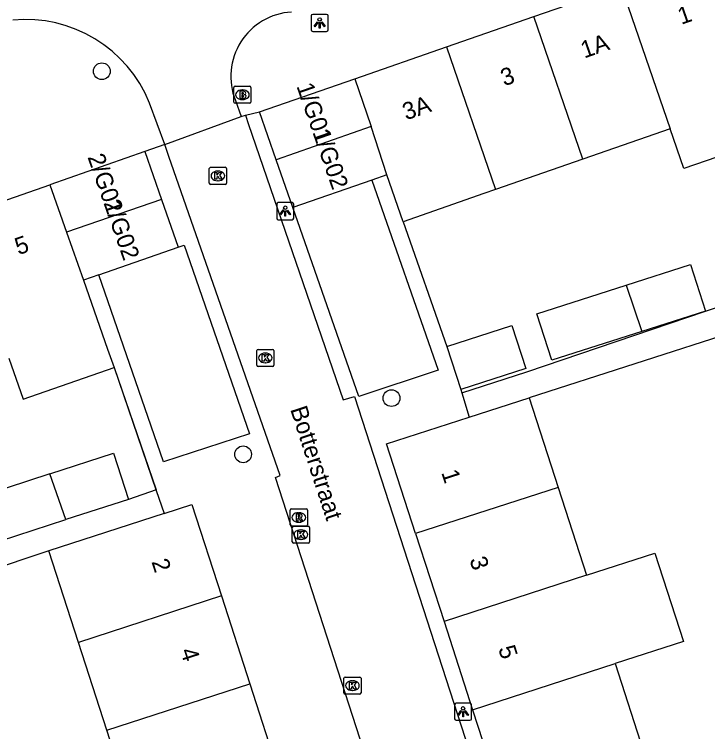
# Model space of a CAD drawing. Extents: x 159377 to 159983, y 382996 to 383595.
# Drawn here: x 159638.52 to 159679.02, y 383252.43 to 383294.33 of the extents above; entities that cross this region are included whole.
import ezdxf

# ---------------------------------------------------------------- set-up
doc = ezdxf.new("R2010")
doc.units = 0
for name, color, linetype in [('IMGEO_Boom', 7, 'Continuous'), ('IMGEO_Brandkraan', 7, 'Continuous'), ('IMGEO_Kolk', 7, 'Continuous'), ('IMGEO_Lichtpunt', 7, 'Continuous'), ('IMGEO_Muur', 7, 'Continuous'), ('IMGEO_Openbare_ruimte_label', 7, 'Continuous'), ('IMGEO_Pand', 7, 'Continuous'), ('IMGEO_Pand_nummerreeks', 7, 'Continuous'), ('IMGEO_Rijbaan_lokaal_open', 7, 'Continuous'), ('IMGEO_Rioolput', 7, 'Continuous'), ('IMGEO_Voetpad_open', 7, 'Continuous')]:
    doc.layers.add(name, color=color, linetype=linetype)

msp = doc.modelspace()

# ---------------------------------------------------------------- linework, layer by layer
at = {"layer": 'IMGEO_Boom'}
for centre in [(159643.634, 383291.001), (159660.553, 383271.913), (159651.886, 383268.63)]:
    msp.add_circle(centre, 0.489, dxfattribs=at)
at = {"layer": 'IMGEO_Brandkraan'}
for p, q in [((159651.418, 383290.129), (159652.27, 383290.129)), ((159651.343, 383289.203), (159651.343, 383290.055)), ((159651.831, 383289.909), (159651.856, 383289.909)), ((159652.344, 383290.055), (159652.344, 383289.203)), ((159651.854, 383289.349), (159651.829, 383289.349)), ((159652.27, 383289.129), (159651.418, 383289.129))]:
    msp.add_line(p, q, dxfattribs=at)
for points in [[(159651.418, 383290.129), (159652.27, 383290.129)], [(159651.343, 383289.203), (159651.343, 383290.055)], [(159651.691, 383289.829), (159651.691, 383289.429), (159651.904, 383289.429)], [(159651.922, 383289.829), (159651.691, 383289.829)], [(159651.87, 383289.748), (159651.816, 383289.748), (159651.816, 383289.672)], [(159651.816, 383289.672), (159651.869, 383289.672)], [(159652.344, 383290.055), (159652.344, 383289.203)], [(159651.878, 383289.596), (159651.816, 383289.596), (159651.816, 383289.515)], [(159651.816, 383289.515), (159651.878, 383289.515)], [(159652.27, 383289.129), (159651.418, 383289.129)]]:
    msp.add_lwpolyline(points, dxfattribs=at)
for centre, radius, start, end in [((159651.42, 383290.053), 0.0765, 91.552, 178.448), ((159651.42, 383290.053), 0.0765, 91.552, 178.448), ((159652.268, 383290.053), 0.0765, 1.552, 88.448), ((159652.268, 383290.053), 0.0765, 1.552, 88.448), ((159651.871, 383289.71), 0.0379, 267.8285, 90.9355), ((159651.926, 383289.684), 0.145, 59.4692, 91.5367), ((159651.951, 383289.731), 0.0922, 285.5137, 58.1501), ((159651.956, 383289.539), 0.105, 301.3115, 78.989), ((159651.879, 383289.555), 0.0404, 269.8759, 90.5077), ((159651.91, 383289.68), 0.251, 268.6676, 293.5347), ((159651.42, 383289.205), 0.0765, 181.552, 268.448), ((159651.42, 383289.205), 0.0765, 181.552, 268.448), ((159652.268, 383289.205), 0.0765, 271.552, 358.448), ((159652.268, 383289.205), 0.0765, 271.552, 358.448)]:
    msp.add_arc(centre, radius, start, end, dxfattribs=at)
for centre, major_axis, ratio, start_param, end_param in [((159651.83, 383289.629), (-0.387, 0.002), 0.722429, 4.712389, 7.853982), ((159651.855, 383289.629), (-0.39, 0.002), 0.717154, 1.570796, 4.712389)]:
    msp.add_ellipse(centre, major_axis=major_axis, ratio=ratio, start_param=start_param, end_param=end_param, dxfattribs=at)
at = {"layer": 'IMGEO_Kolk'}
for p, q in [((159649.912, 383284.465), (159649.912, 383285.317)), ((159649.987, 383285.391), (159650.839, 383285.391)), ((159650.4, 383285.171), (159650.425, 383285.171)), ((159650.913, 383285.317), (159650.913, 383284.465)), ((159650.839, 383284.391), (159649.987, 383284.391)), ((159650.423, 383284.611), (159650.398, 383284.611)), ((159652.684, 383273.835), (159652.684, 383274.687)), ((159652.759, 383274.761), (159653.611, 383274.761)), ((159653.685, 383274.687), (159653.685, 383273.835)), ((159653.172, 383274.541), (159653.197, 383274.541)), ((159653.611, 383273.761), (159652.759, 383273.761)), ((159653.195, 383273.981), (159653.17, 383273.981)), ((159654.759, 383263.514), (159654.759, 383264.366)), ((159654.834, 383264.44), (159655.686, 383264.44)), ((159655.247, 383264.22), (159655.272, 383264.22)), ((159655.76, 383264.366), (159655.76, 383263.514)), ((159655.686, 383263.44), (159654.834, 383263.44)), ((159655.27, 383263.66), (159655.245, 383263.66)), ((159657.772, 383254.698), (159657.772, 383255.55)), ((159657.847, 383255.624), (159658.699, 383255.624)), ((159658.26, 383255.404), (159658.285, 383255.404)), ((159658.773, 383255.55), (159658.773, 383254.698)), ((159658.699, 383254.624), (159657.847, 383254.624)), ((159658.283, 383254.844), (159658.258, 383254.844))]:
    msp.add_line(p, q, dxfattribs=at)
for points in [[(159649.912, 383284.465), (159649.912, 383285.317)], [(159649.987, 383285.391), (159650.839, 383285.391)], [(159650.233, 383285.091), (159650.356, 383285.091), (159650.356, 383284.94), (159650.486, 383285.091), (159650.65, 383285.091), (159650.504, 383284.94), (159650.657, 383284.691), (159650.505, 383284.691), (159650.42, 383284.855), (159650.356, 383284.788), (159650.356, 383284.691), (159650.233, 383284.691), (159650.233, 383285.091)], [(159650.913, 383285.317), (159650.913, 383284.465)], [(159650.839, 383284.391), (159649.987, 383284.391)], [(159652.684, 383273.835), (159652.684, 383274.687)], [(159652.759, 383274.761), (159653.611, 383274.761)], [(159653.685, 383274.687), (159653.685, 383273.835)], [(159653.005, 383274.461), (159653.128, 383274.461), (159653.128, 383274.31), (159653.258, 383274.461), (159653.422, 383274.461), (159653.276, 383274.31), (159653.429, 383274.061), (159653.277, 383274.061), (159653.192, 383274.225), (159653.128, 383274.158), (159653.128, 383274.061), (159653.005, 383274.061), (159653.005, 383274.461)], [(159653.611, 383273.761), (159652.759, 383273.761)], [(159654.759, 383263.514), (159654.759, 383264.366)], [(159654.834, 383264.44), (159655.686, 383264.44)], [(159655.08, 383264.14), (159655.203, 383264.14), (159655.203, 383263.989), (159655.333, 383264.14), (159655.497, 383264.14), (159655.351, 383263.989), (159655.504, 383263.74), (159655.352, 383263.74), (159655.267, 383263.904), (159655.203, 383263.837), (159655.203, 383263.74), (159655.08, 383263.74), (159655.08, 383264.14)], [(159655.76, 383264.366), (159655.76, 383263.514)], [(159655.686, 383263.44), (159654.834, 383263.44)], [(159657.772, 383254.698), (159657.772, 383255.55)], [(159657.847, 383255.624), (159658.699, 383255.624)], [(159658.093, 383255.324), (159658.216, 383255.324), (159658.216, 383255.173), (159658.346, 383255.324), (159658.51, 383255.324), (159658.364, 383255.173), (159658.517, 383254.924), (159658.365, 383254.924), (159658.28, 383255.088), (159658.216, 383255.021), (159658.216, 383254.924), (159658.093, 383254.924), (159658.093, 383255.324)], [(159658.773, 383255.55), (159658.773, 383254.698)], [(159658.699, 383254.624), (159657.847, 383254.624)]]:
    msp.add_lwpolyline(points, dxfattribs=at)
for centre, start, end in [((159649.989, 383285.315), 91.552, 178.448), ((159649.989, 383285.315), 91.552, 178.448), ((159650.837, 383285.315), 1.552, 88.448), ((159650.837, 383285.315), 1.552, 88.448), ((159649.989, 383284.467), 181.552, 268.448), ((159649.989, 383284.467), 181.552, 268.448), ((159650.837, 383284.467), 271.552, 358.448), ((159650.837, 383284.467), 271.552, 358.448), ((159652.761, 383274.685), 91.552, 178.448), ((159652.761, 383274.685), 91.552, 178.448), ((159653.609, 383274.685), 1.552, 88.448), ((159653.609, 383274.685), 1.552, 88.448), ((159652.761, 383273.837), 181.552, 268.448), ((159652.761, 383273.837), 181.552, 268.448), ((159653.609, 383273.837), 271.552, 358.448), ((159653.609, 383273.837), 271.552, 358.448), ((159654.836, 383264.364), 91.552, 178.448), ((159654.836, 383264.364), 91.552, 178.448), ((159655.684, 383264.364), 1.552, 88.448), ((159655.684, 383264.364), 1.552, 88.448), ((159654.836, 383263.516), 181.552, 268.448), ((159654.836, 383263.516), 181.552, 268.448), ((159655.684, 383263.516), 271.552, 358.448), ((159655.684, 383263.516), 271.552, 358.448), ((159657.849, 383255.548), 91.552, 178.448), ((159657.849, 383255.548), 91.552, 178.448), ((159658.697, 383255.548), 1.552, 88.448), ((159658.697, 383255.548), 1.552, 88.448), ((159657.849, 383254.7), 181.552, 268.448), ((159657.849, 383254.7), 181.552, 268.448), ((159658.697, 383254.7), 271.552, 358.448), ((159658.697, 383254.7), 271.552, 358.448)]:
    msp.add_arc(centre, 0.0765, start, end, dxfattribs=at)
for centre, major_axis, ratio, start_param, end_param in [((159650.399, 383284.891), (-0.387, 0.002), 0.722429, 4.712389, 7.853982), ((159650.424, 383284.891), (-0.39, 0.002), 0.717154, 1.570796, 4.712389), ((159653.171, 383274.261), (-0.387, 0.002), 0.722429, 4.712389, 7.853982), ((159653.196, 383274.261), (-0.39, 0.002), 0.717154, 1.570796, 4.712389), ((159655.246, 383263.94), (-0.387, 0.002), 0.722429, 4.712389, 7.853982), ((159655.271, 383263.94), (-0.39, 0.002), 0.717154, 1.570796, 4.712389), ((159658.259, 383255.124), (-0.387, 0.002), 0.722429, 4.712389, 7.853982), ((159658.284, 383255.124), (-0.39, 0.002), 0.717154, 1.570796, 4.712389)]:
    msp.add_ellipse(centre, major_axis=major_axis, ratio=ratio, start_param=start_param, end_param=end_param, dxfattribs=at)
at = {"layer": 'IMGEO_Lichtpunt'}
for p, q in [((159656.761, 383294.325), (159655.953, 383294.325)), ((159656.761, 383294.325), (159655.953, 383294.325)), ((159655.859, 383294.23), (159655.859, 383293.423)), ((159655.859, 383294.23), (159655.859, 383293.423)), ((159656.855, 383293.423), (159656.855, 383294.23)), ((159656.855, 383293.423), (159656.855, 383294.23)), ((159655.953, 383293.329), (159656.761, 383293.329)), ((159655.953, 383293.329), (159656.761, 383293.329)), ((159653.847, 383283.235), (159653.847, 383282.428)), ((159653.847, 383283.235), (159653.847, 383282.428)), ((159654.749, 383283.33), (159653.941, 383283.33)), ((159654.749, 383283.33), (159653.941, 383283.33)), ((159654.843, 383282.428), (159654.843, 383283.235)), ((159654.843, 383282.428), (159654.843, 383283.235)), ((159653.941, 383282.334), (159654.749, 383282.334)), ((159653.941, 383282.334), (159654.749, 383282.334)), ((159665.138, 383254.092), (159664.33, 383254.092)), ((159665.138, 383254.092), (159664.33, 383254.092)), ((159664.236, 383253.997), (159664.236, 383253.19)), ((159664.236, 383253.997), (159664.236, 383253.19)), ((159665.232, 383253.19), (159665.232, 383253.997)), ((159665.232, 383253.19), (159665.232, 383253.997)), ((159664.33, 383253.096), (159665.138, 383253.096)), ((159664.33, 383253.096), (159665.138, 383253.096))]:
    msp.add_line(p, q, dxfattribs=at)
for points in [[(159656.233, 383293.894), (159656.272, 383293.866), (159656.084, 383293.604), (159656.046, 383293.631), (159656.233, 383293.894)], [(159656.335, 383293.846), (159656.382, 383293.846), (159656.382, 383293.524), (159656.335, 383293.524), (159656.335, 383293.846)], [(159656.445, 383293.866), (159656.483, 383293.893), (159656.67, 383293.631), (159656.631, 383293.603), (159656.445, 383293.866)], [(159654.221, 383282.899), (159654.26, 383282.871), (159654.072, 383282.609), (159654.034, 383282.636), (159654.221, 383282.899)], [(159654.323, 383282.851), (159654.37, 383282.851), (159654.37, 383282.529), (159654.323, 383282.529), (159654.323, 383282.851)], [(159654.433, 383282.871), (159654.471, 383282.898), (159654.658, 383282.636), (159654.619, 383282.608), (159654.433, 383282.871)], [(159664.61, 383253.661), (159664.649, 383253.633), (159664.461, 383253.371), (159664.423, 383253.398), (159664.61, 383253.661)], [(159664.822, 383253.633), (159664.86, 383253.66), (159665.047, 383253.398), (159665.008, 383253.37), (159664.822, 383253.633)], [(159664.712, 383253.613), (159664.759, 383253.613), (159664.759, 383253.291), (159664.712, 383253.291), (159664.712, 383253.613)]]:
    msp.add_lwpolyline(points, dxfattribs=at)
for centre in [(159656.358, 383294.028), (159654.346, 383283.033), (159664.735, 383253.795)]:
    msp.add_circle(centre, 0.0994, dxfattribs=at)
for centre, start, end in [((159655.953, 383294.23), 90, 180), ((159655.953, 383294.23), 90, 180), ((159656.761, 383294.23), 0, 90), ((159656.761, 383294.23), 0, 90), ((159655.953, 383293.423), 180, 270), ((159655.953, 383293.423), 180, 270), ((159656.761, 383293.423), 270, 0), ((159656.761, 383293.423), 270, 360), ((159653.941, 383283.235), 90, 180), ((159653.941, 383283.235), 90, 180), ((159654.749, 383283.235), 0, 90), ((159654.749, 383283.235), 0, 90), ((159653.941, 383282.428), 180, 270), ((159653.941, 383282.428), 180, 270), ((159654.749, 383282.428), 270, 0), ((159654.749, 383282.428), 270, 360), ((159664.33, 383253.997), 90, 180), ((159664.33, 383253.997), 90, 180), ((159665.138, 383253.997), 0, 90), ((159665.138, 383253.997), 0, 90), ((159664.33, 383253.19), 180, 270), ((159664.33, 383253.19), 180, 270), ((159665.138, 383253.19), 270, 0), ((159665.138, 383253.19), 270, 360)]:
    msp.add_arc(centre, 0.0946, start, end, dxfattribs=at)
at = {"layer": 'IMGEO_Muur'}
for points in [[(159661.227, 383282.213), (159663.782, 383274.935)], [(159644.346, 383273.697), (159646.813, 383266.522)]]:
    msp.add_lwpolyline(points, dxfattribs=at)
at = {"layer": 'IMGEO_Pand'}
for points in [[(159668.862, 383294.193), (159673.964, 383295.964)], [(159673.964, 383295.964), (159676.828, 383287.631)], [(159663.771, 383292.425), (159668.862, 383294.193)], [(159671.727, 383285.86), (159668.862, 383294.193)], [(159658.405, 383290.562), (159663.771, 383292.425)], [(159663.771, 383292.425), (159666.636, 383284.092)], [(159652.848, 383288.632), (159658.405, 383290.562)], [(159658.405, 383290.562), (159659.344, 383287.841), (159659.368, 383287.766)], [(159653.818, 383285.838), (159652.848, 383288.632)], [(159659.368, 383287.766), (159653.818, 383285.838)], [(159660.276, 383284.951), (159659.368, 383287.766)], [(159676.828, 383287.631), (159671.727, 383285.86)], [(159682.85, 383287.113), (159677.624, 383285.316), (159676.828, 383287.631)], [(159646.153, 383286.308), (159640.596, 383284.369)], [(159646.153, 383286.308), (159647.125, 383283.52)], [(159654.788, 383283.045), (159653.818, 383285.838)], [(159671.727, 383285.86), (159666.636, 383284.092)], [(159659.403, 383284.648), (159654.788, 383283.045)], [(159660.276, 383284.951), (159659.403, 383284.648)], [(159661.227, 383282.213), (159660.276, 383284.951)], [(159635.29, 383282.518), (159640.596, 383284.369)], [(159640.596, 383284.369), (159641.574, 383281.6)], [(159666.636, 383284.092), (159665.951, 383283.854), (159661.227, 383282.213)], [(159647.125, 383283.52), (159641.574, 383281.6)], [(159647.125, 383283.52), (159648.098, 383280.733)], [(159641.574, 383281.6), (159642.565, 383278.803)], [(159643.458, 383279.114), (159648.098, 383280.733)], [(159674.255, 383278.506), (159678.019, 383279.71), (159678.888, 383276.992)], [(159643.458, 383279.114), (159642.565, 383278.803)], [(159642.565, 383278.803), (159643.506, 383276.105), (159643.971, 383274.771), (159644.346, 383273.697)], [(159675.184, 383275.807), (159669.914, 383274.121), (159669.044, 383276.839), (159674.255, 383278.506)], [(159674.255, 383278.506), (159675.184, 383275.807)], [(159678.888, 383276.992), (159675.184, 383275.807)], [(159663.782, 383274.935), (159667.58, 383276.163), (159668.398, 383273.636), (159664.598, 383272.413)], [(159663.782, 383274.935), (159664.598, 383272.413)], [(159638.205, 383274.255), (159639.045, 383271.847), (159644.346, 383273.697)], [(159665.094, 383270.795), (159668.593, 383271.927)], [(159668.593, 383271.927), (159670.285, 383266.696)], [(159661.961, 383263.998), (159660.268, 383269.234), (159665.094, 383270.795)], [(159640.593, 383267.486), (159644.321, 383268.692), (159645.192, 383265.998)], [(159640.593, 383267.486), (159636.837, 383266.271), (159637.708, 383263.577)], [(159641.535, 383264.815), (159640.593, 383267.486)], [(159670.285, 383266.696), (159661.961, 383263.998)], [(159670.285, 383266.696), (159671.945, 383261.564)], [(159645.192, 383265.998), (159641.535, 383264.815)], [(159647.277, 383265.179), (159648.894, 383265.702), (159650.622, 383260.358)], [(159647.277, 383265.179), (159642.52, 383263.641), (159640.533, 383262.998)], [(159637.708, 383263.577), (159641.535, 383264.815)], [(159661.961, 383263.998), (159663.622, 383258.865)], [(159642.263, 383257.649), (159640.533, 383262.998)], [(159671.945, 383261.564), (159675.94, 383262.86), (159677.608, 383257.706), (159673.612, 383256.411)], [(159671.945, 383261.564), (159663.622, 383258.865)], [(159650.622, 383260.358), (159642.263, 383257.649)], [(159650.622, 383260.358), (159652.281, 383255.229)], [(159663.622, 383258.865), (159665.288, 383253.713)], [(159643.922, 383252.521), (159642.263, 383257.649)], [(159665.288, 383253.713), (159673.612, 383256.411)], [(159673.612, 383256.411), (159675.276, 383251.267)], [(159643.922, 383252.521), (159652.281, 383255.229)], [(159652.281, 383255.229), (159653.942, 383250.092)], [(159665.288, 383253.713), (159666.494, 383250), (159666.955, 383248.57)], [(159645.582, 383247.384), (159644.737, 383249.999), (159643.922, 383252.521)]]:
    msp.add_lwpolyline(points, dxfattribs=at)
at = {"layer": 'IMGEO_Rijbaan_lokaal_open'}
for points in [[(159651.438, 383289.296), (159651.778, 383288.352)], [(159647.315, 383286.718), (159646.422, 383289.143)], [(159651.778, 383288.352), (159652.017, 383288.429)], [(159652.017, 383288.429), (159652.205, 383287.893), (159657.725, 383271.809), (159658.393, 383272.015), (159665.513, 383250), (159669.446, 383237.835), (159668.26, 383237.434), (159668.65, 383236.234)], [(159647.315, 383286.718), (159651.778, 383288.352)], [(159663.772, 383234.65), (159663.364, 383235.901), (159663.852, 383236.075), (159659.36, 383250), (159653.786, 383267.274), (159654.055, 383267.387), (159647.551, 383286.019), (159647.315, 383286.718)]]:
    msp.add_lwpolyline(points, dxfattribs=at)
for centre, radius, start, end in [((159654.94, 383290.697), 3.772, 93.506, 201.8118), ((159639.178, 383286.208), 7.816, 22.0545, 95.4458)]:
    msp.add_arc(centre, radius, start, end, dxfattribs=at)
at = {"layer": 'IMGEO_Rioolput'}
for p, q in [((159654.639, 383264.516), (159654.639, 383265.368)), ((159654.714, 383265.442), (159655.566, 383265.442)), ((159655.64, 383265.368), (159655.64, 383264.516)), ((159655.127, 383265.222), (159655.152, 383265.222)), ((159655.15, 383264.662), (159655.125, 383264.662)), ((159655.566, 383264.442), (159654.714, 383264.442))]:
    msp.add_line(p, q, dxfattribs=at)
for points in [[(159654.639, 383264.516), (159654.639, 383265.368)], [(159654.714, 383265.442), (159655.566, 383265.442)], [(159655.64, 383265.368), (159655.64, 383264.516)], [(159655.228, 383265.14), (159654.976, 383265.142), (159654.976, 383264.742)], [(159655.154, 383265.061), (159655.1, 383265.061), (159655.1, 383264.98)], [(159655.1, 383264.98), (159655.152, 383264.98)], [(159654.976, 383264.742), (159655.1, 383264.742), (159655.1, 383264.904), (159655.111, 383264.904)], [(159655.158, 383264.875), (159655.229, 383264.742), (159655.369, 383264.742), (159655.304, 383264.868)], [(159655.566, 383264.442), (159654.714, 383264.442)]]:
    msp.add_lwpolyline(points, dxfattribs=at)
for centre, radius, start, end in [((159654.716, 383265.366), 0.0765, 91.552, 178.448), ((159654.716, 383265.366), 0.0765, 91.552, 178.448), ((159655.564, 383265.366), 0.0765, 1.552, 88.448), ((159655.564, 383265.366), 0.0765, 1.552, 88.448), ((159655.136, 383265.169), 0.19, 274.7715, 282.9687), ((159655.16, 383264.965), 0.0964, 77.0061, 93.1865), ((159655.174, 383265.022), 0.0378, 276.6634, 79.6772), ((159655.227, 383265.03), 0.109, 350.3612, 89.416), ((159655.225, 383265.03), 0.112, 277.5842, 350.9817), ((159654.716, 383264.518), 0.0765, 181.552, 268.448), ((159654.716, 383264.518), 0.0765, 181.552, 268.448), ((159655.11, 383264.851), 0.0533, 26.0293, 88.6989), ((159655.209, 383264.815), 0.108, 29.5134, 73.7905), ((159655.564, 383264.518), 0.0765, 271.552, 358.448), ((159655.564, 383264.518), 0.0765, 271.552, 358.448)]:
    msp.add_arc(centre, radius, start, end, dxfattribs=at)
for centre, major_axis, ratio, start_param, end_param in [((159655.126, 383264.942), (-0.387, 0.002), 0.722429, 4.712389, 7.853982), ((159655.151, 383264.942), (-0.39, 0.002), 0.717154, 1.570796, 4.712389)]:
    msp.add_ellipse(centre, major_axis=major_axis, ratio=ratio, start_param=start_param, end_param=end_param, dxfattribs=at)
at = {"layer": 'IMGEO_Voetpad_open'}
for points in [[(159652.017, 383288.429), (159652.848, 383288.632)], [(159647.315, 383286.718), (159646.153, 383286.308)], [(159659.403, 383284.648), (159663.288, 383273.551), (159658.649, 383272.016), (159654.788, 383283.045)], [(159661.227, 383282.213), (159663.782, 383274.935)], [(159648.098, 383280.733), (159648.437, 383280.851), (159652.26, 383269.832), (159647.245, 383268.195), (159643.458, 383279.114)], [(159678.888, 383276.992), (159681.963, 383278.01)], [(159664.66, 383272.22), (159668.458, 383273.449), (159678.888, 383276.992)], [(159680.943, 383275.903), (159668.593, 383271.927)], [(159644.346, 383273.697), (159646.802, 383266.554)], [(159664.598, 383272.413), (159664.66, 383272.22)], [(159664.66, 383272.22), (159665.094, 383270.795)], [(159646.802, 383266.554), (159645.192, 383265.998)], [(159646.802, 383266.554), (159646.813, 383266.522), (159647.277, 383265.179)], [(159640.533, 383262.998), (159629.312, 383259.246)]]:
    msp.add_lwpolyline(points, dxfattribs=at)

# ---------------------------------------------------------------- texts
at = {"layer": 'IMGEO_Openbare_ruimte_label'}
msp.add_text('Botterstraat', height=1, rotation=288.0546, dxfattribs=at).set_placement((159654.628, 383271.265))
at = {"layer": 'IMGEO_Pand_nummerreeks'}
for s, rotation, p in [('1', 19.1482, (159677.48, 383293.713)), ('1A', 19.1488, (159671.815, 383291.746)), ('3', 19.1488, (159667.132, 383290.12)), ('1/G01', 289.1488, (159654.993, 383290.137)), ('3A', 19.1449, (159661.403, 383288.131)), ('1/G02', 289.1488, (159655.925, 383287.454)), ('2/G01', 289.2328, (159642.788, 383285.994)), ('2/G02', 289.2328, (159643.723, 383283.317)), ('5', 19.2313, (159638.763, 383280.256)), ('1', 287.9151, (159663.454, 383267.568)), ('2', 287.8724, (159646.526, 383262.359)), ('3', 287.9162, (159665.098, 383262.485)), ('5', 287.9162, (159666.776, 383257.295)), ('4', 287.8724, (159648.203, 383257.156))]:
    msp.add_text(s, height=1, rotation=rotation, dxfattribs=at).set_placement(p)

doc.saveas('drawing.dxf')
